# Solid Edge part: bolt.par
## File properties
Author: Sarvanan
Template: sync ansi part.par
Last saved by: Cadcim
Revision: 2
Application: Solid Edge
Accuracy: 0.990
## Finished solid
Body 1: solid body, 11 faces, 21 edges, 12 vertices.
  Faces by surface: plane 9, cone 1, cylinder 1
  Edges by curve: line 12, intersection 6, circle 3
Bounding box of the edges (mm): 7.620 x 8.799 x 81.280, from (-0.0184, -5.4708, -78.74) to (7.6016, 3.328, 2.54).
Cylindrical faces by radius (mm): R3.3834 x1
Conical faces (half-angle, radius in mm at the cone's reference point): 45 deg R4.3994 x1
Planar faces by outward normal: +x 1, +z 1, -x 1, -z 2, oblique 4
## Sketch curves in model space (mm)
circle centre (3.7916, -1.0714, 2.54) radius 3.302
line (3.7916, -1.0714, 2.54) -> (7.175, -1.0714, 2.54)
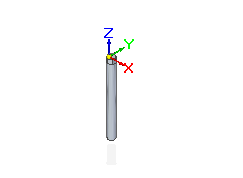
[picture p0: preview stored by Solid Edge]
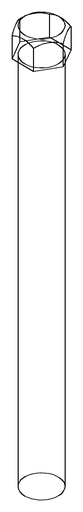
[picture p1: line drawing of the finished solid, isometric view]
